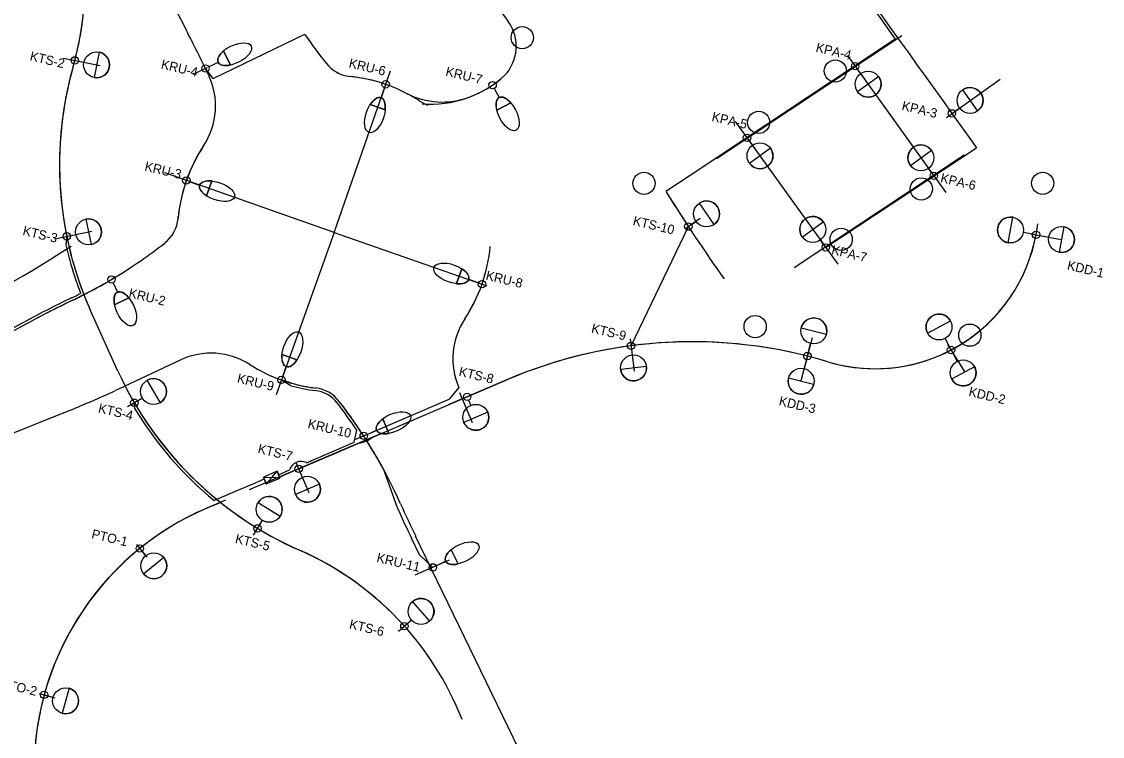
# Model space of a CAD drawing. Extents: x 0 to 511877, y 0 to 6211921.
# Drawn here: x 511731.4 to 511877.3, y 6211771.4 to 6211867.9 of the extents above; entities that cross this region are included whole.
import ezdxf

# ---------------------------------------------------------------- set-up
doc = ezdxf.new("R2010")
doc.units = 0
for name, color, linetype in [('Help', 7, 'Continuous'), ('Lys Kommunalt', 7, 'Continuous'), ('TV_U_LYS_Ledn-', 7, 'Continuous'), ('TV_U_LYS_Ledn-ror', 7, 'Continuous'), ('TV_U_LYS_Mastenummer', 7, 'Continuous'), ('TV_U_LYS_Nyx330-Trafiksti', 7, 'Continuous'), ('TV_U_LYS_Nyx330-Trafiksti-x2', 7, 'Continuous'), ('TV_U_LYS_Nyx450-Rundkørsel', 7, 'Continuous'), ('TV_U_LYS_Skab-', 7, 'Continuous')]:
    doc.layers.add(name, color=color, linetype=linetype)

msp = doc.modelspace()

# ---------------------------------------------------------------- linework, layer by layer
at = {"layer": 'Help'}
for p, q in [((511737.87, 6211897.5), (511753.64, 6211866.78)), ((511850.25, 6211865.99), (511825.26, 6211849.37)), ((511737.07, 6211862.97), (511742.04, 6211861.96)), ((511842.93, 6211863.32), (511856.21, 6211844.85)), ((511756.48, 6211861.68), (511754.57, 6211860.75)), ((511773.63, 6211839.45), (511781.22, 6211861.26)), ((511856.28, 6211854.97), (511863.55, 6211860.14)), ((511827.79, 6211854.42), (511841.63, 6211835.15)), ((511835.74, 6211834.73), (511858.68, 6211849.91)), ((511773.63, 6211839.45), (511750.76, 6211847.47)), ((511821.12, 6211840), (511823.06, 6211841.35)), ((511735.94, 6211838.6), (511740.91, 6211839.61)), ((511773.63, 6211839.45), (511765.8, 6211817.54)), ((511773.63, 6211839.45), (511794.22, 6211832.24)), ((511867.66, 6211839.27), (511871.78, 6211838.5)), ((511731.6, 6211826.85), (511712.88, 6211816.67)), ((511813.59, 6211825.07), (511814.11, 6211820.73)), ((511838.18, 6211825.23), (511836.63, 6211819.43)), ((511856.45, 6211824.32), (511858.77, 6211820.6)), ((511752.86, 6211822.22), (511745.26, 6211818.65)), ((511797.03, 6211819.58), (511789.04, 6211816.17)), ((511745.74, 6211815.93), (511747.77, 6211817.11)), ((511790.54, 6211817.82), (511792.26, 6211813.79)), ((511737.13, 6211815.1), (511717.35, 6211807.17)), ((511780.13, 6211812.36), (511762.16, 6211804.69)), ((511777.85, 6211812.09), (511776.49, 6211811.49)), ((511768.47, 6211808.39), (511770.19, 6211804.36)), ((511758.97, 6211803.32), (511756.46, 6211802.25)), ((511762.75, 6211798.61), (511763.97, 6211800.61)), ((511801.3, 6211764.11), (511784.63, 6211798.45)), ((511746.95, 6211797.35), (511748.33, 6211795.64)), ((511789.15, 6211795.2), (511784.5, 6211793.17)), ((511782.33, 6211785.61), (511784.08, 6211787.17)), ((511733.79, 6211777.22), (511735.91, 6211776.64))]:
    msp.add_line(p, q, dxfattribs=at)
for centre, radius, start, end in [((511698.44, 6211873.22), 41.55, 344.1199, 31.5529), ((511492.79, 6211732.81), 293.25, 25.873, 27.1845), ((511785, 6211848.59), 48.45, 164.1199, 203.872), ((511747.87, 6211856.52), 9.75, 326.4699, 25.873), ((511776.27, 6211865.22), 4.75, 241.178, 264.1389), ((511786.65, 6211871.6), 14.85, 265.6673, 312.541), ((511773.63, 6211839.45), 21.15, 57.4742, 84.1389), ((511790.24, 6211865.51), 9.75, 237.4742, 245.9742), ((511773.63, 6211839.45), 21.15, 146.4699, 174.8984), ((512002.24, 6211959.14), 216.39, 211.9545, 215.6047), ((511747.83, 6211841.76), 4.75, 308.0405, 354.8984), ((511846.65, 6211843.16), 22.11, 253.2522, 353.3164), ((511657.36, 6211960.49), 147.05, 284.2876, 303.3127), ((511709.01, 6211891.37), 67.75, 307.6597, 308.0405), ((511773.63, 6211839.45), 21.15, 326.526, 354.8764), ((511709.01, 6211891.37), 67.75, 295.6773, 302.8126), ((511804.34, 6211693.1), 152.25, 115.6773, 118.5372), ((511821.98, 6211761.17), 63.52, 77.2222, 113.1329), ((511821.98, 6211761.17), 63.52, 73.2522, 113.1329), ((511757.01, 6211813.4), 9.75, 57.4742, 115.1994), ((511773.63, 6211839.45), 21.15, 237.4742, 263.1955), ((511788.49, 6211840.89), 48.45, 204.5723, 246.233), ((511680.44, 6211956.41), 152.25, 291.861, 295.1994), ((511770.56, 6211813.74), 4.75, 37.7479, 83.1955), ((511720.74, 6211775.17), 67.75, 24.0765, 37.7479), ((511921.61, 6211864.92), 152.25, 204.0765, 205.8873), ((511771.57, 6211766.89), 38.45, 113.1329, 182.9937), ((511752.22, 6211758.53), 41.55, 21.4307, 66.233)]:
    msp.add_arc(centre, radius, start, end, dxfattribs=at)
at = {"layer": 'Lys Kommunalt'}
for centre in [(511799.02, 6211865.74), (511841.29, 6211861.24), (511830.95, 6211854.29), (511815.47, 6211846.06), (511869.27, 6211846.08), (511852.89, 6211845.32), (511842.08, 6211838.51), (511830.47, 6211826.74), (511859.45, 6211825.58)]:
    msp.add_circle(centre, 1.5, dxfattribs=at)
at = {"layer": 'TV_U_LYS_Ledn-'}
for p, q in [((511747.17, 6211879.38), (511753.64, 6211866.78)), ((511794.22, 6211871.96), (511797.14, 6211867.89)), ((511849.39, 6211865.54), (511823.2, 6211848.12)), ((511757.31, 6211860.24), (511756.26, 6211861.57)), ((511839.98, 6211837.41), (511860.34, 6211850.88)), ((511752.56, 6211841.34), (511752.59, 6211841.66)), ((511813.71, 6211824.15), (511821.45, 6211840.23)), ((511737.53, 6211838.92), (511737.42, 6211837.76)), ((511744.13, 6211833.44), (511743.56, 6211833.1)), ((511731.43, 6211827.16), (511727.69, 6211825.13)), ((511731.6, 6211826.85), (511726.2, 6211823.91)), ((511767.87, 6211819.1), (511766.51, 6211819.54)), ((511766.51, 6211819.54), (511767.77, 6211818.77)), ((511790.47, 6211818.51), (511789.17, 6211816.92)), ((511789.45, 6211816.34), (511797.03, 6211819.58)), ((511746.73, 6211815.64), (511746.65, 6211816.46)), ((511776.33, 6211811.12), (511776.69, 6211812.76)), ((511769.89, 6211808.37), (511776.33, 6211811.12)), ((511768.84, 6211807.54), (511776.98, 6211811.02)), ((511766.11, 6211806.75), (511767.59, 6211807.39)), ((511768.84, 6211807.54), (511766.25, 6211806.43)), ((511780.23, 6211807.6), (511782.15, 6211802.3)), ((511764.2, 6211806.15), (511762.32, 6211805.35)), ((511785.17, 6211795.92), (511784.08, 6211798.18)), ((511786.95, 6211794.24), (511785.17, 6211795.92))]:
    msp.add_line(p, q, dxfattribs=at)
for points in [[(511842.85, 6211875.27), (511843.06, 6211874.98), (511844.23, 6211873.33), (511845.41, 6211871.7), (511846.55, 6211870.1), (511847.71, 6211868.48), (511848.89, 6211866.83), (511850.06, 6211865.2), (511851.24, 6211863.57), (511852.4, 6211861.95), (511852.98, 6211861.15)], [(511843.57, 6211873.65), (511845.12, 6211871.49), (511846.27, 6211869.9), (511847.43, 6211868.27), (511849.39, 6211865.54)], [(511857.03, 6211855.51), (511858.18, 6211853.89), (511859.37, 6211852.24), (511860.34, 6211850.88)]]:
    msp.add_lwpolyline(points, dxfattribs=at)
for centre, radius, start, end in [((511698.44, 6211873.22), 41.55, 344.1199, 18.4149), ((511492.79, 6211732.81), 293.25, 25.873, 27.1845), ((511792.48, 6211864.55), 5.73, 315.9303, 35.6812), ((511825.77, 6211904.19), 67.75, 214.129, 218.2171), ((511776.27, 6211865.22), 4.75, 218.2171, 264.1389), ((511785, 6211848.59), 48.45, 164.1199, 192.8079), ((511747.87, 6211856.52), 9.75, 326.4699, 25.873), ((511786.65, 6211871.6), 14.85, 290.4556, 312.541), ((511773.63, 6211839.45), 21.15, 62.4567, 84.1389), ((511788.21, 6211867.42), 10.38, 242.4567, 290.4556), ((511773.63, 6211839.45), 21.15, 146.4699, 174.0203), ((512002.57, 6211959.36), 216.79, 211.855, 213.3362), ((511747.83, 6211841.76), 4.75, 308.0405, 354.8984), ((511773.63, 6211839.45), 21.15, 174.8983, 174.8984), ((511846.65, 6211843.16), 22.11, 253.2522, 349.4913), ((511709.01, 6211891.37), 67.75, 301.2255, 308.0405), ((511785, 6211848.59), 48.8, 197.9463, 200.8617), ((511785, 6211848.59), 48.45, 197.8987, 201.9062), ((511773.63, 6211839.45), 21.15, 326.526, 340.7012), ((511803.74, 6211694.2), 151.35, 115.6773, 118.5372), ((511803.74, 6211694.2), 151, 115.6773, 118.5372), ((511708.41, 6211892.47), 68.65, 295.6773, 296.8338), ((511708.41, 6211892.47), 69, 295.6773, 296.6155), ((511799.4, 6211822.41), 9.75, 146.526, 203.5966), ((511821.98, 6211761.17), 63.52, 73.2522, 113.1329), ((511788.49, 6211840.89), 48.45, 206.5413, 231.2259), ((511773.63, 6211839.45), 21.5, 254.2012, 263.1955), ((511773.63, 6211839.45), 21.15, 254.2012, 263.1955), ((511770.56, 6211813.74), 4.75, 37.7479, 83.1955), ((511770.56, 6211813.74), 4.4, 37.7479, 83.1955), ((511788.49, 6211840.89), 48.8, 211.1615, 230.4612), ((511720.74, 6211775.17), 67.4, 33.9005, 37.7479), ((511720.74, 6211775.17), 67.75, 32.8819, 37.7479), ((511776.5, 6211814.59), 3.6, 277.6037, 308.6622), ((511769.16, 6211806.89), 1.65, 63.9791, 162.2868), ((511771.57, 6211766.89), 38.45, 110.2939, 182.9937), ((511921.61, 6211864.92), 152.87, 204.1835, 205.8873), ((511788.49, 6211840.89), 48.45, 237.232, 246.233), ((511752.22, 6211758.53), 41.55, 41.9566, 66.233)]:
    msp.add_arc(centre, radius, start, end, dxfattribs=at)
at = {"layer": 'TV_U_LYS_Ledn-ror'}
for p, q in [((511757.31, 6211860.24), (511769.69, 6211866.18)), ((511823.13, 6211848.08), (511818.43, 6211844.95)), ((511744.43, 6211820.74), (511740.7, 6211828.99)), ((511777.62, 6211811.99), (511789.17, 6211816.92)), ((511778.76, 6211811.78), (511789.45, 6211816.34)), ((511762.29, 6211805.34), (511757.42, 6211803.26))]:
    msp.add_line(p, q, dxfattribs=at)
msp.add_lwpolyline([(511852.98, 6211861.15), (511853.56, 6211860.34), (511854.72, 6211858.72), (511855.88, 6211857.11), (511857.03, 6211855.51)], dxfattribs=at)
for centre, radius, start, end in [((511785, 6211848.59), 48.8, 192.8275, 197.9463), ((511785, 6211848.59), 48.45, 192.8079, 197.8987), ((511708.4, 6211892.47), 69, 296.6155, 300.6357), ((511785, 6211848.59), 48.45, 201.9062, 203.872), ((511788.49, 6211840.89), 48.45, 204.5723, 206.5413), ((511720.74, 6211775.17), 67.75, 28.5961, 32.8819), ((511788.49, 6211840.89), 48.45, 231.2259, 237.232)]:
    msp.add_arc(centre, radius, start, end, dxfattribs=at)
at = {"layer": 'TV_U_LYS_Nyx330-Trafiksti'}
for p, q in [((511741.91, 6211863.78), (511741.22, 6211860.34)), ((511741.91, 6211863.78), (511741.91, 6211863.78)), ((511739.11, 6211862.56), (511739.85, 6211862.41)), ((511844.26, 6211861.48), (511844.7, 6211860.87)), ((511847.15, 6211860.47), (511844.3, 6211858.43)), ((511847.15, 6211860.47), (511847.15, 6211860.47)), ((511858.47, 6211858.67), (511860.5, 6211855.82)), ((511858.47, 6211858.67), (511858.47, 6211858.67)), ((511857.44, 6211855.8), (511858.05, 6211856.23)), ((511829.66, 6211851.82), (511830.1, 6211851.21)), ((511832.54, 6211850.81), (511829.7, 6211848.76)), ((511832.54, 6211850.81), (511832.54, 6211850.81)), ((511851.42, 6211848.48), (511854.26, 6211850.54)), ((511851.42, 6211848.48), (511851.42, 6211848.48)), ((511854.31, 6211847.48), (511853.87, 6211848.09)), ((511822.92, 6211843.38), (511824.91, 6211840.5)), ((511822.92, 6211843.38), (511822.92, 6211843.38)), ((511740.12, 6211841.24), (511740.82, 6211837.81)), ((511740.12, 6211841.24), (511740.12, 6211841.24)), ((511821.86, 6211840.51), (511822.48, 6211840.94)), ((511836.82, 6211838.82), (511839.66, 6211840.88)), ((511738.02, 6211839.02), (511738.75, 6211839.17)), ((511836.82, 6211838.82), (511836.82, 6211838.82)), ((511839.71, 6211837.82), (511839.27, 6211838.43)), ((511813.76, 6211823.65), (511813.85, 6211822.9)), ((511815.79, 6211821.37), (511812.31, 6211820.96)), ((511815.79, 6211821.37), (511815.79, 6211821.37)), ((511748.36, 6211819.49), (511750.13, 6211816.46)), ((511748.36, 6211819.49), (511748.36, 6211819.49)), ((511747.08, 6211816.71), (511747.73, 6211817.09)), ((511791.78, 6211816.79), (511792.07, 6211816.1)), ((511794.37, 6211815.18), (511791.15, 6211813.8)), ((511794.37, 6211815.18), (511794.37, 6211815.18)), ((511769.03, 6211807.08), (511769.33, 6211806.39)), ((511771.63, 6211805.46), (511768.41, 6211804.09)), ((511771.63, 6211805.46), (511771.63, 6211805.46)), ((511763.36, 6211802.99), (511766.35, 6211801.16)), ((511763.36, 6211802.99), (511763.36, 6211802.99)), ((511763.55, 6211799.94), (511763.95, 6211800.58)), ((511747.71, 6211796.4), (511748.18, 6211795.82)), ((511750.65, 6211795.56), (511747.92, 6211793.36)), ((511750.65, 6211795.56), (511750.65, 6211795.56)), ((511784.2, 6211789.61), (511786.52, 6211786.99)), ((511784.2, 6211789.61), (511784.2, 6211789.61)), ((511783.49, 6211786.64), (511784.05, 6211787.14)), ((511737.84, 6211777.93), (511736.91, 6211774.55)), ((511737.84, 6211777.93), (511737.84, 6211777.93)), ((511734.96, 6211776.9), (511735.69, 6211776.7))]:
    msp.add_line(p, q, dxfattribs=at)
for centre, radius in [((511741.56, 6211862.06), 1.75), ((511738.62, 6211862.66), 0.5), ((511843.97, 6211861.89), 0.5), ((511845.72, 6211859.45), 1.75), ((511859.48, 6211857.25), 1.75), ((511857.03, 6211855.51), 0.5), ((511829.37, 6211852.22), 0.5), ((511831.12, 6211849.79), 1.75), ((511852.84, 6211849.51), 1.75), ((511854.6, 6211847.08), 0.5), ((511823.91, 6211841.94), 1.75), ((511740.47, 6211839.52), 1.75), ((511821.45, 6211840.23), 0.5), ((511838.24, 6211839.85), 1.75), ((511737.53, 6211838.92), 0.5), ((511840, 6211837.42), 0.5), ((511813.7, 6211824.15), 0.5), ((511814.05, 6211821.16), 1.75), ((511749.24, 6211817.97), 1.75), ((511746.65, 6211816.46), 0.5), ((511791.58, 6211817.25), 0.5), ((511792.76, 6211814.49), 1.75), ((511768.84, 6211807.54), 0.5), ((511770.02, 6211804.78), 1.75), ((511764.86, 6211802.07), 1.75), ((511763.29, 6211799.51), 0.5), ((511747.4, 6211796.79), 0.5), ((511749.28, 6211794.46), 1.75), ((511785.36, 6211788.3), 1.75), ((511783.11, 6211786.31), 0.5), ((511734.48, 6211777.03), 0.5), ((511737.37, 6211776.24), 1.75)]:
    msp.add_circle(centre, radius, dxfattribs=at)
for centre, start, end in [((511741.56, 6211862.06), 258.5805, 78.5106), ((511845.72, 6211859.45), 215.7332, 35.6632), ((511859.48, 6211857.25), 305.4622, 125.3922), ((511831.12, 6211849.79), 215.7332, 35.6632), ((511852.84, 6211849.51), 35.9602, 215.8902), ((511823.91, 6211841.94), 304.7843, 124.7143), ((511740.47, 6211839.52), 281.5656, 101.4956), ((511838.24, 6211839.85), 35.9602, 215.8902), ((511814.05, 6211821.16), 186.707, 6.637), ((511749.24, 6211817.97), 300.2994, 120.2294), ((511792.76, 6211814.49), 203.169, 23.099), ((511770.02, 6211804.78), 203.169, 23.099), ((511764.86, 6211802.07), 328.6887, 148.6187), ((511749.28, 6211794.46), 219.0037, 38.9337), ((511785.36, 6211788.3), 311.6652, 131.5953), ((511737.37, 6211776.24), 254.7647, 74.6947)]:
    msp.add_arc(centre, 1.75, start, end, dxfattribs=at)
at = {"layer": 'TV_U_LYS_Nyx330-Trafiksti-x2'}
for p, q in [((511864.62, 6211838.05), (511865.26, 6211841.49)), ((511872.15, 6211840.21), (511871.52, 6211836.77)), ((511872.15, 6211840.21), (511872.15, 6211840.21)), ((511868.39, 6211839.13), (511866.67, 6211839.45)), ((511868.39, 6211839.13), (511870.11, 6211838.81)), ((511864.62, 6211838.05), (511864.62, 6211838.05)), ((511853.74, 6211825.87), (511856.84, 6211827.5)), ((511836.68, 6211826.58), (511840.08, 6211825.73)), ((511836.68, 6211826.58), (511836.68, 6211826.58)), ((511853.74, 6211825.87), (511853.74, 6211825.87)), ((511837.52, 6211822.76), (511837.95, 6211824.46)), ((511856.91, 6211823.58), (511856.1, 6211825.13)), ((511837.52, 6211822.76), (511837.09, 6211821.06)), ((511856.91, 6211823.58), (511857.73, 6211822.03)), ((511860.09, 6211821.29), (511856.99, 6211819.66)), ((511860.09, 6211821.29), (511860.09, 6211821.29)), ((511838.36, 6211818.93), (511834.97, 6211819.79)), ((511838.36, 6211818.93), (511838.36, 6211818.93))]:
    msp.add_line(p, q, dxfattribs=at)
for centre, radius in [((511864.94, 6211839.77), 1.75), ((511871.83, 6211838.49), 1.75), ((511868.39, 6211839.13), 0.5), ((511838.38, 6211826.15), 1.75), ((511855.29, 6211826.68), 1.75), ((511837.52, 6211822.76), 0.5), ((511856.91, 6211823.58), 0.5), ((511858.54, 6211820.48), 1.75), ((511836.67, 6211819.36), 1.75)]:
    msp.add_circle(centre, radius, dxfattribs=at)
for centre, start, end in [((511864.94, 6211839.77), 79.532, 259.4621), ((511871.83, 6211838.49), 259.532, 79.4621), ((511838.38, 6211826.15), 345.8783, 165.8084), ((511855.29, 6211826.68), 27.6964, 207.6264), ((511858.54, 6211820.48), 207.6964, 27.6264), ((511836.67, 6211819.36), 165.8783, 345.8084)]:
    msp.add_arc(centre, 1.75, start, end, dxfattribs=at)
at = {"layer": 'TV_U_LYS_Nyx450-Rundkørsel'}
for p, q in [((511758.71, 6211863.96), (511759.65, 6211862.04)), ((511759.65, 6211862.04), (511758.71, 6211863.96)), ((511756.71, 6211861.79), (511757.97, 6211862.41)), ((511780.42, 6211858.96), (511779.96, 6211857.63)), ((511795.25, 6211858.89), (511795.9, 6211857.64)), ((511780.52, 6211856), (511778.5, 6211856.7)), ((511778.5, 6211856.7), (511780.52, 6211856)), ((511797.48, 6211856.94), (511795.58, 6211855.95)), ((511795.58, 6211855.95), (511797.48, 6211856.94)), ((511754.14, 6211846.29), (511755.47, 6211845.83)), ((511757.1, 6211846.39), (511756.4, 6211844.37)), ((511756.4, 6211844.37), (511757.1, 6211846.39)), ((511790.16, 6211832.53), (511790.87, 6211834.55)), ((511790.87, 6211834.55), (511790.16, 6211832.53)), ((511793.12, 6211832.63), (511791.79, 6211833.09)), ((511743.78, 6211832.65), (511744.37, 6211831.38)), ((511745.92, 6211830.61), (511743.98, 6211829.69)), ((511743.98, 6211829.69), (511745.92, 6211830.61)), ((511766.6, 6211822.97), (511768.61, 6211822.25)), ((511768.61, 6211822.25), (511766.6, 6211822.97)), ((511766.68, 6211820.01), (511767.15, 6211821.33)), ((511780.18, 6211814.27), (511781.03, 6211812.31)), ((511781.03, 6211812.31), (511780.18, 6211814.27)), ((511778.08, 6211812.19), (511779.36, 6211812.75)), ((511789.42, 6211796.63), (511790.35, 6211794.7)), ((511790.35, 6211794.7), (511789.42, 6211796.63)), ((511787.4, 6211794.46), (511788.67, 6211795.07))]:
    msp.add_line(p, q, dxfattribs=at)
for centre in [(511756.26, 6211861.57), (511780.58, 6211859.43), (511795.02, 6211859.33), (511753.67, 6211846.45), (511743.56, 6211833.1), (511793.59, 6211832.46), (511766.51, 6211819.54), (511777.62, 6211811.99), (511786.95, 6211794.24)]:
    msp.add_circle(centre, 0.5, dxfattribs=at)
for centre, major_axis in [((511760.2, 6211863.5), (2.23, 1.09)), ((511779.14, 6211855.28), (-0.81, -2.35)), ((511797.05, 6211855.44), (1.15, -2.2)), ((511757.82, 6211845.01), (2.35, -0.81)), ((511789.45, 6211833.91), (-2.35, 0.82)), ((511745.43, 6211829.13), (1.06, -2.25)), ((511767.98, 6211823.67), (0.83, 2.34)), ((511781.64, 6211813.75), (2.28, 1)), ((511790.9, 6211796.16), (2.23, 1.09))]:
    msp.add_ellipse(centre, major_axis=major_axis, ratio=0.483744, dxfattribs=at)
for centre, major_axis in [((511760.2, 6211863.5), (2.23, 1.09)), ((511779.14, 6211855.28), (-0.81, -2.35)), ((511797.05, 6211855.44), (1.15, -2.2)), ((511757.82, 6211845.01), (2.35, -0.81)), ((511789.45, 6211833.91), (-2.35, 0.82)), ((511745.43, 6211829.13), (1.06, -2.25)), ((511767.98, 6211823.67), (0.83, 2.34)), ((511781.64, 6211813.75), (2.28, 1)), ((511790.9, 6211796.16), (2.23, 1.09))]:
    msp.add_ellipse(centre, major_axis=major_axis, ratio=0.483744, start_param=2.042184, end_param=4.239581, dxfattribs=at)
at = {"layer": 'TV_U_LYS_Skab-'}
for points in [[(511764.08, 6211806.42), (511764.47, 6211805.5), (511766.31, 6211806.29), (511765.92, 6211807.21)], [(511766.31, 6211806.29), (511765.2, 6211806.36), (511765.92, 6211807.21)], [(511764.08, 6211806.42), (511765.2, 6211806.36), (511764.47, 6211805.5)]]:
    msp.add_lwpolyline(points, close=True, dxfattribs=at)

# ---------------------------------------------------------------- texts
at = {"layer": 'TV_U_LYS_Mastenummer'}
for s, p in [('KPA-4', (511838.57, 6211863.85)), ('KTS-2', (511732.47, 6211862.69)), ('KRU-4', (511750.17, 6211861.59)), ('KRU-6', (511775.53, 6211861.74)), ('KRU-7', (511788.59, 6211860.61)), ('KPA-3', (511850.18, 6211855.99)), ('KPA-5', (511824.52, 6211854.51)), ('KRU-3', (511747.96, 6211847.81)), ('KPA-6', (511855.4, 6211846.25)), ('KTS-3', (511731.5, 6211839.12)), ('KTS-10', (511813.88, 6211840.47)), ('KPA-7', (511840.69, 6211836.54)), ('KDD-1', (511872.51, 6211834.47)), ('KRU-8', (511794.02, 6211833.09)), ('KRU-2', (511745.81, 6211830.71)), ('KTS-9', (511808.27, 6211825.95)), ('KTS-8', (511790.38, 6211820.12)), ('KRU-9', (511760.45, 6211819.2)), ('KDD-2', (511859.21, 6211817.4)), ('KDD-3', (511833.59, 6211816.15)), ('KTS-4', (511741.7, 6211815.18)), ('KRU-10', (511769.98, 6211813.07)), ('KTS-7', (511763.24, 6211809.7)), ('PTO-1', (511740.79, 6211798.2)), ('KTS-5', (511760.18, 6211797.56)), ('KRU-11', (511779.28, 6211795)), ('KTS-6', (511775.59, 6211786.02)), ('PTO-2', (511728.55, 6211778.03))]:
    msp.add_text(s, height=1.25, rotation=346.664, dxfattribs=at).set_placement(p)

doc.saveas('drawing.dxf')
